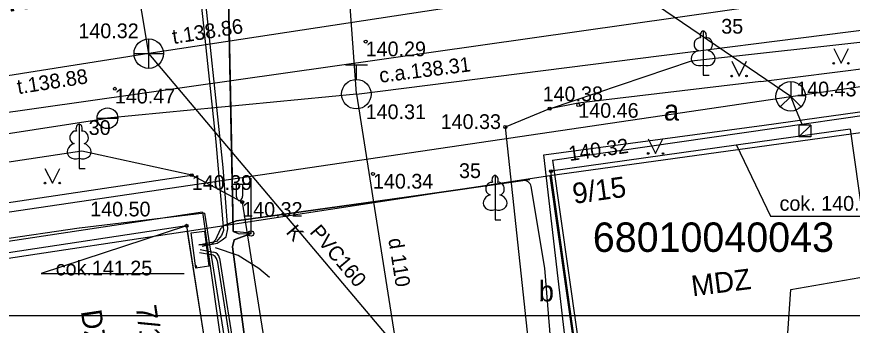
# Model space of a CAD drawing. Extents: x 728710 to 728960, y 272811 to 273475.
# Drawn here: x 728793.07 to 728821.41, y 273201.73 to 273212.21 of the extents above; entities that cross this region are included whole.
import ezdxf

# ---------------------------------------------------------------- set-up
doc = ezdxf.new("R2010")
doc.units = 0
for name, color, linetype in [('58', 7, 'Continuous'), ('GEOD_ELEM_####_TKST_#', 7, 'Continuous'), ('Level 15', 7, 'Continuous'), ('Level 16', 7, 'Continuous'), ('Level 17', 7, 'Continuous'), ('Level 18', 7, 'Continuous'), ('Level 23', 7, 'Continuous'), ('Level 26', 7, 'Continuous'), ('Level 29', 7, 'Continuous'), ('Level 3', 7, 'Continuous'), ('Level 36', 7, 'Continuous'), ('Level 39', 7, 'Continuous'), ('Level 4', 7, 'Continuous'), ('Level 41', 7, 'Continuous'), ('Level 45', 7, 'Continuous'), ('Level 46', 7, 'Continuous'), ('Level 47', 7, 'Continuous'), ('Level 48', 7, 'Continuous'), ('Level 50', 7, 'Continuous'), ('Level 54', 7, 'Continuous'), ('Level 55', 7, 'Continuous'), ('Level 56', 7, 'Continuous'), ('Level 57', 7, 'Continuous'), ('Level 58', 7, 'Continuous'), ('Level 59', 7, 'Continuous'), ('Level 60', 7, 'Continuous'), ('Level 62', 7, 'Continuous'), ('Level 9', 7, 'Continuous'), ('RAMI_PLAN_####_TKST_#', 7, 'Continuous'), ('RAMI_UZMR_####_####_#', 7, 'Continuous'), ('RELJ_ELEM_####_####_#', 7, 'Continuous'), ('RELJ_NOGA_####_####_#', 7, 'Continuous'), ('ROBZ_ELEM_####_####_#', 7, 'Continuous'), ('ROBZ_KADS_####_TKST_#', 7, 'Continuous'), ('ROBZ_UZMR_####_####_#', 7, 'Continuous'), ('TERT_ELEM_####_####_#', 7, 'Continuous'), ('TERT_KONT_####_####_#', 7, 'Continuous')]:
    doc.layers.add(name, color=color, linetype=linetype)

msp = doc.modelspace()

# ---------------------------------------------------------------- linework, layer by layer
at = {"layer": 'GEOD_ELEM_####_TKST_#'}
for points in [[(728801.008, 273204.855), (728800.415, 273204.912), (728800.181, 273216.709), (728800.141, 273216.891)], [(728806.989, 273165.064), (728806.014, 273164.984), (728805.919, 273164.996), (728805.829, 273165.094), (728801.63, 273195.055), (728800.391, 273204.396), (728800.452, 273204.629), (728801.02, 273204.847)]]:
    msp.add_lwpolyline(points, dxfattribs=at)
at = {"layer": 'Level 15'}
msp.add_lwpolyline([(728799.439, 273204.923), (728799.592, 273203.733), (728799.145, 273203.675), (728798.992, 273204.865)], close=True, dxfattribs=at)
at = {"layer": 'Level 16'}
for points in [[(728798.647, 273218.321), (728798.79, 273217.505), (728799.373, 273212.209), (728799.822, 273207.956), (728800.089, 273204.952), (728800.017, 273204.781), (728799.85, 273204.575), (728799.252, 273204.449)], [(728799.366, 273204.415), (728799.867, 273204.517), (728800.041, 273204.634), (728800.179, 273204.73), (728800.235, 273205.009), (728800.072, 273207.092), (728799.365, 273213.863), (728798.795, 273218.34)], [(728801.652, 273203.35), (728801.288, 273203.656), (728800.589, 273204.096), (728799.814, 273204.359)], [(728799.15, 273203.777), (728799.183, 273203.666)]]:
    msp.add_lwpolyline(points, dxfattribs=at)
at = {"layer": 'Level 17'}
for p, q in [((728804.594, 273209.577), (728829.118, 273212.697)), ((728774.223, 273205.388), (728796.151, 273208.761))]:
    msp.add_line(p, q, dxfattribs=at)
for points in [[(728803.013, 273231.194), (728804.591, 273209.598), (728804.594, 273209.577)], [(728804.594, 273209.577), (728796.15, 273208.762)], [(728804.594, 273209.577), (728806.57, 273197.07)]]:
    msp.add_lwpolyline(points, dxfattribs=at)
at = {"layer": 'Level 18'}
msp.add_lwpolyline([(728775.408, 273206.499), (728828.88, 273214.109)], dxfattribs=at)
at = {"layer": 'Level 23'}
for points in [[(728797.551, 273210.954), (728796.382, 273217.977)], [(728828.61, 273215.701), (728797.551, 273210.954), (728774.123, 273207.246)], [(728810.106, 273196.087), (728797.551, 273210.954)]]:
    msp.add_lwpolyline(points, dxfattribs=at)
at = {"layer": 'Level 26'}
for p, q in [((728801.02, 273204.847), (728801.02, 273206.73)), ((728801.02, 273206.514), (728800.385, 273206.509)), ((728800.52, 273206.51), (728800.52, 273206.118)), ((728800.73, 273206.512), (728800.73, 273206.118))]:
    msp.add_line(p, q, dxfattribs=at)
msp.add_circle((728801.02, 273204.847), 0.09, dxfattribs=at)
msp.add_ellipse((728800.625, 273206.118), major_axis=(0, 0.151), ratio=0.695971, start_param=1.570796, end_param=4.712389, dxfattribs=at)
at = {"layer": 'Level 29'}
for p, q in [((728797.551, 273210.454), (728797.551, 273211.454)), ((728797.051, 273210.954), (728798.051, 273210.954))]:
    msp.add_line(p, q, dxfattribs=at)
msp.add_circle((728797.551, 273210.954), 0.5, dxfattribs=at)
at = {"layer": 'Level 3'}
for p, q in [((728821.345, 273208.386), (728811.193, 273206.959)), ((728821.345, 273208.386), (728822.042, 273203.423)), ((728812.098, 273200.51), (728811.193, 273206.959)), ((728798.835, 273205.109), (728792.334, 273204.124)), ((728798.835, 273205.109), (728799.854, 273198.536))]:
    msp.add_line(p, q, dxfattribs=at)
at = {"layer": 'Level 36'}
msp.add_lwpolyline([(728800.032, 273205.094), (728800.529, 273205.273), (728806.294, 273206.075), (728810.478, 273206.685)], dxfattribs=at)
at = {"layer": 'Level 39'}
for p, q in [((728804.219, 273210.577), (728804.969, 273210.577)), ((728804.594, 273210.077), (728804.594, 273210.577)), ((728795.8, 273208.762), (728796.5, 273208.762)), ((728796.15, 273208.761), (728796.15, 273208.762))]:
    msp.add_line(p, q, dxfattribs=at)
for centre, radius in [((728804.594, 273209.577), 0.5), ((728796.151, 273208.761), 0.351)]:
    msp.add_circle(centre, radius, dxfattribs=at)
at = {"layer": 'Level 4'}
for p, q in [((728818.311, 273210.011), (728822.238, 273210.509)), ((728818.311, 273210.011), (728812.113, 273209.275)), ((728818.428, 273208.52), (728822.382, 273209.083)), ((728810.951, 273207.517), (728818.428, 273208.52)), ((728790.803, 273205.597), (728799.004, 273206.826)), ((728800.722, 273205.914), (728799.011, 273206.827)), ((728799.446, 273205.539), (728795.197, 273205.031)), ((728795.195, 273205.024), (728792.259, 273204.602))]:
    msp.add_line(p, q, dxfattribs=at)
for points in [[(728812.113, 273209.275), (728811.146, 273209.084), (728809.644, 273208.462)], [(728809.644, 273208.462), (728810.915, 273196.542), (728813.126, 273181.312)], [(728812.193, 273196.782), (728810.951, 273207.517)], [(728800.722, 273205.914), (728802.266, 273196.137), (728804.601, 273179.443)], [(728799.446, 273205.539), (728800.992, 273195.724), (728803.086, 273179.05)]]:
    msp.add_lwpolyline(points, dxfattribs=at)
at = {"layer": 'Level 41'}
for points in [[(728819.726, 273208.522), (728819.527, 273209.009), (728819.326, 273209.502), (728808.867, 273216.627), (728806.045, 273235.742)], [(728792.122, 273205.478), (728819.326, 273209.502), (728829.414, 273210.952)]]:
    msp.add_lwpolyline(points, dxfattribs=at)
at = {"layer": 'Level 45'}
for points in [[(728811.146, 273209.084), (728815.965, 273210.711), (728829.206, 273212.18)], [(728799.011, 273206.827), (728795.279, 273207.647), (728784.404, 273206), (728774.293, 273204.089)]]:
    msp.add_lwpolyline(points, dxfattribs=at)
at = {"layer": 'Level 46'}
msp.add_line((728819.326, 273209.502), (728819.68, 273209.148), dxfattribs=at)
msp.add_lwpolyline([(728819.326, 273210.002), (728819.326, 273209.502), (728818.972, 273209.148)], dxfattribs=at)
msp.add_circle((728819.326, 273209.502), 0.5, dxfattribs=at)
at = {"layer": 'Level 47'}
for p, q in [((728820.004, 273208.522), (728819.603, 273208.522)), ((728819.603, 273208.522), (728819.603, 273208.128))]:
    msp.add_line(p, q, dxfattribs=at)
msp.add_lwpolyline([(728819.603, 273208.128), (728820.004, 273208.522), (728820.004, 273208.128)], close=True, dxfattribs=at)
at = {"layer": 'Level 48'}
for centre in [(728804.909, 273211.363), (728796.401, 273209.761), (728811.153, 273209.085), (728812.12, 273209.209), (728809.644, 273208.462), (728799.011, 273206.827), (728805.156, 273206.871), (728811.193, 273206.959), (728800.722, 273205.914), (728798.835, 273205.109)]:
    msp.add_circle(centre, 0.05, dxfattribs=at)
at = {"layer": 'Level 9'}
for points in [[(728817.481, 273207.843), (728818.644, 273205.437), (728822.493, 273205.437)], [(728798.835, 273205.109), (728793.899, 273203.485), (728798.755, 273203.485)]]:
    msp.add_lwpolyline(points, dxfattribs=at)
at = {"layer": 'RAMI_PLAN_####_TKST_#'}
for points in [[(728728.89, 273202.048), (728728.89, 273475.126), (728912.915, 273475.126), (728912.915, 273202.048)], [(728709.938, 272811.037), (728959.516, 272811.036), (728959.516, 273202.048), (728709.939, 273202.048)]]:
    msp.add_lwpolyline(points, close=True, dxfattribs=at)
at = {"layer": 'RAMI_UZMR_####_####_#'}
msp.add_lwpolyline([(728838.026, 273158.297), (728833.202, 273166.507), (728833.235, 273168.344), (728821.579, 273179.812), (728818.749, 273194.545), (728819.331, 273202.951), (728829.731, 273204.761), (728829.577, 273209.987), (728827.575, 273221.822), (728826.396, 273224.831), (728813.325, 273229.618), (728810.773, 273260.978), (728802.611, 273315.901)], dxfattribs=at)
at = {"layer": 'RELJ_ELEM_####_####_#'}
for points in [[(728799.963, 273216.945), (728800.141, 273216.891), (728800.181, 273216.709), (728800.371, 273207.399), (728800.415, 273204.912), (728800.619, 273204.837), (728801.02, 273204.847)], [(728801.02, 273204.847), (728800.592, 273204.683), (728800.452, 273204.629), (728800.391, 273204.396), (728801.63, 273195.055), (728805.803, 273165.389), (728805.847, 273165.074), (728805.919, 273164.996), (728806.11, 273164.973), (728807.003, 273165.091)]]:
    msp.add_lwpolyline(points, dxfattribs=at)
at = {"layer": 'ROBZ_ELEM_####_####_#'}
for points in [[(728811.24, 273207.332), (728829.577, 273209.987)], [(728811.24, 273207.332), (728816.642, 273169.324)], [(728799.369, 273205.575), (728774.417, 273201.799)], [(728799.369, 273205.575), (728804.76, 273167.644)]]:
    msp.add_lwpolyline(points, dxfattribs=at)
at = {"layer": 'ROBZ_UZMR_####_####_#'}
for p, q in [((728821.78, 273208.272), (728811.158, 273206.807)), ((728811.158, 273206.807), (728798.857, 273204.918)), ((728811.158, 273206.807), (728812.087, 273200.226)), ((728798.857, 273204.918), (728778.166, 273201.794)), ((728798.857, 273204.918), (728799.91, 273198.314))]:
    msp.add_line(p, q, dxfattribs=at)
at = {"layer": 'TERT_ELEM_####_####_#'}
for p, q in [((728799.275, 273204.201), (728799.664, 273204.132)), ((728799.292, 273204.299), (728799.752, 273204.218))]:
    msp.add_line(p, q, dxfattribs=at)
for points in [[(728810.236, 273206.65), (728806.294, 273206.075), (728800.529, 273205.273), (728800.129, 273205.129)], [(728811.191, 273201.159), (728810.98, 273203.671), (728810.518, 273206.443)], [(728799.988, 273205.001), (728799.801, 273204.606)], [(728799.58, 273204.463), (728799.25, 273204.458)], [(728799.868, 273203.925), (728800.411, 273200.491), (728801.537, 273192.703), (728803.228, 273181.337), (728804.575, 273171.658), (728805.512, 273165.011)], [(728799.956, 273204.011), (728800.509, 273200.505), (728801.635, 273192.717), (728803.326, 273181.351), (728804.675, 273171.672), (728805.612, 273165.025)]]:
    msp.add_lwpolyline(points, dxfattribs=at)
for centre, start, end in [((728810.272, 273206.402), 9.4562, 98.2949), ((728800.214, 273204.894), 109.807, 154.6891), ((728799.575, 273204.713), 270.9968, 334.6891), ((728799.621, 273203.886), 8.979, 79.9931), ((728799.709, 273203.972), 8.979, 79.9931)]:
    msp.add_arc(centre, 0.25, start, end, dxfattribs=at)
at = {"layer": 'TERT_KONT_####_####_#'}
for p, q in [((728820.783, 273211.125), (728821.033, 273210.625)), ((728821.033, 273210.625), (728821.283, 273211.125)), ((728816.359, 273210.566), (728816.359, 273210.219)), ((728817.324, 273210.692), (728817.574, 273210.192)), ((728817.574, 273210.192), (728817.824, 273210.692)), ((728816.359, 273210.219), (728816.559, 273210.219)), ((728814.491, 273208.065), (728814.741, 273207.565)), ((728814.741, 273207.565), (728814.991, 273208.065)), ((728795.189, 273207.401), (728795.189, 273207.054)), ((728794.031, 273207.059), (728794.281, 273206.559)), ((728794.281, 273206.559), (728794.531, 273207.059)), ((728795.189, 273207.054), (728795.389, 273207.054)), ((728809.297, 273205.663), (728809.297, 273205.316)), ((728809.297, 273205.316), (728809.497, 273205.316))]:
    msp.add_line(p, q, dxfattribs=at)
for points in [[(728816.359, 273211.719), (728816.359, 273210.566)], [(728816.449, 273211.487), (728816.448, 273211.488)], [(728795.189, 273208.554), (728795.189, 273207.401)], [(728795.279, 273208.322), (728795.278, 273208.323)], [(728809.297, 273206.816), (728809.297, 273205.663)], [(728809.387, 273206.584), (728809.386, 273206.585)]]:
    msp.add_lwpolyline(points, dxfattribs=at)
for centre, radius in [((728820.783, 273210.625), 0.028), ((728821.283, 273210.625), 0.0263), ((728817.324, 273210.191), 0.028), ((728817.824, 273210.191), 0.0263), ((728814.491, 273207.564), 0.028), ((728814.991, 273207.564), 0.0263), ((728794.031, 273206.558), 0.028), ((728794.531, 273206.558), 0.0263)]:
    msp.add_circle(centre, radius, dxfattribs=at)
for centre, major_axis, ratio, start_param, end_param in [((728816.359, 273211.569), (0, -0.15), 0.707107, 3.14537, 5.287485), ((728816.359, 273211.569), (0, -0.15), 0.707107, 0.995701, 3.137816), ((728816.231, 273211.274), (-0.039, -0.212), 0.861323, 3.141593, 6.283185), ((728816.487, 273211.274), (0.039, -0.212), 0.861323, 0, 3.141593), ((728816.269, 273210.812), (0.307, 0.095), 0.814445, 1.570796, 4.752015), ((728816.449, 273210.812), (-0.307, 0.095), 0.814445, 1.531171, 4.712389), ((728795.189, 273208.404), (0, -0.15), 0.707107, 3.14537, 5.287485), ((728795.189, 273208.404), (0, -0.15), 0.707107, 0.995701, 3.137816), ((728795.061, 273208.11), (-0.039, -0.212), 0.861323, 3.141593, 6.283185), ((728795.317, 273208.11), (0.039, -0.212), 0.861323, 0, 3.141593), ((728795.099, 273207.647), (0.307, 0.095), 0.814445, 1.570796, 4.752015), ((728795.279, 273207.647), (-0.307, 0.095), 0.814445, 1.531171, 4.712389), ((728809.169, 273206.371), (-0.039, -0.212), 0.861323, 3.141593, 6.283185), ((728809.297, 273206.666), (0, -0.15), 0.707107, 3.14537, 5.287485), ((728809.297, 273206.666), (0, -0.15), 0.707107, 0.995701, 3.137816), ((728809.425, 273206.371), (0.039, -0.212), 0.861323, 0, 3.141593), ((728809.207, 273205.909), (0.307, 0.095), 0.814445, 1.570796, 4.752015), ((728809.387, 273205.909), (-0.307, 0.095), 0.814445, 1.531171, 4.712389)]:
    msp.add_ellipse(centre, major_axis=major_axis, ratio=ratio, start_param=start_param, end_param=end_param, dxfattribs=at)

# ---------------------------------------------------------------- texts
at = {"layer": '58'}
msp.add_text(' 140.43', height=0.5, dxfattribs=at).set_placement((728819.326, 273209.502))
at = {"layer": 'Level 39'}
msp.add_text('140.31', height=0.5, dxfattribs=at).set_placement((728804.909, 273208.73))
at = {"layer": 'Level 50'}
for s, p in [('cok. 140.49', (728818.947, 273205.62)), ('cok.141.25', (728794.397, 273203.424))]:
    msp.add_text(s, height=0.5, dxfattribs=at).set_placement(p)
at = {"layer": 'Level 54'}
msp.add_text('Baznīcas iela', height=1, rotation=9.6084, dxfattribs=at).set_placement((728786.999, 273211.385))
at = {"layer": 'Level 55'}
for s, rotation, p in [('c.a.138.31', 7.2509, (728805.398, 273209.962)), ('d 110', 278.9766, (728805.676, 273204.655))]:
    msp.add_text(s, height=0.5, rotation=rotation, dxfattribs=at).set_placement(p)
at = {"layer": 'Level 56'}
msp.add_text(' 140.32', height=0.5, dxfattribs=at).set_placement((728794.979, 273211.478))
at = {"layer": 'Level 57'}
for s, p in [('140.29', (728804.909, 273210.863)), ('140.47', (728796.401, 273209.261)), ('140.38', (728810.912, 273209.337)), ('140.46', (728812.12, 273208.776)), ('140.33', (728807.453, 273208.395)), ('140.34', (728805.156, 273206.371)), ('140.39', (728799.011, 273206.327)), (' 140.50', (728795.38, 273205.427)), ('140.32', (728800.722, 273205.414))]:
    msp.add_text(s, height=0.5, dxfattribs=at).set_placement(p)
msp.add_text(' 140.32', height=0.5, rotation=7.9021, dxfattribs=at).set_placement((728811.639, 273207.281))
at = {"layer": 'Level 58'}
for s, p in [('a', (728815.021, 273208.682)), ('b', (728810.776, 273202.539))]:
    msp.add_text(s, height=0.7, dxfattribs=at).set_placement(p)
at = {"layer": 'Level 59'}
for s, rotation, p in [('MDZ', 7.236, (728815.999, 273202.712)), ('DZ', 278.489, (728795.245, 273202.211))]:
    msp.add_text(s, height=0.7, rotation=rotation, dxfattribs=at).set_placement(p)
at = {"layer": 'Level 60'}
for s, rotation, p in [('t.138.86', 8.993, (728798.389, 273211.277)), ('t.138.88', 8.993, (728793.125, 273209.574)), ('K', 310.179, (728802.182, 273204.878)), ('PVC160', 310.179, (728802.984, 273204.883))]:
    msp.add_text(s, height=0.5, rotation=rotation, dxfattribs=at).set_placement(p)
at = {"layer": 'Level 62'}
for s, rotation, p in [('9/15', 7.835, (728811.972, 273205.85)), ('7/18', 278.489, (728797.106, 273202.367))]:
    msp.add_text(s, height=0.7, rotation=rotation, dxfattribs=at).set_placement(p)
at = {"layer": 'RELJ_NOGA_####_####_#'}
for s, p in [('35', (728816.969, 273211.632)), ('30', (728795.515, 273208.193)), ('35', (728808.075, 273206.73))]:
    msp.add_text(s, height=0.5, dxfattribs=at).set_placement(p)
at = {"layer": 'ROBZ_KADS_####_TKST_#'}
msp.add_text('68010040043', height=1, dxfattribs=at).set_placement((728812.612, 273204.222))

doc.saveas('drawing.dxf')
